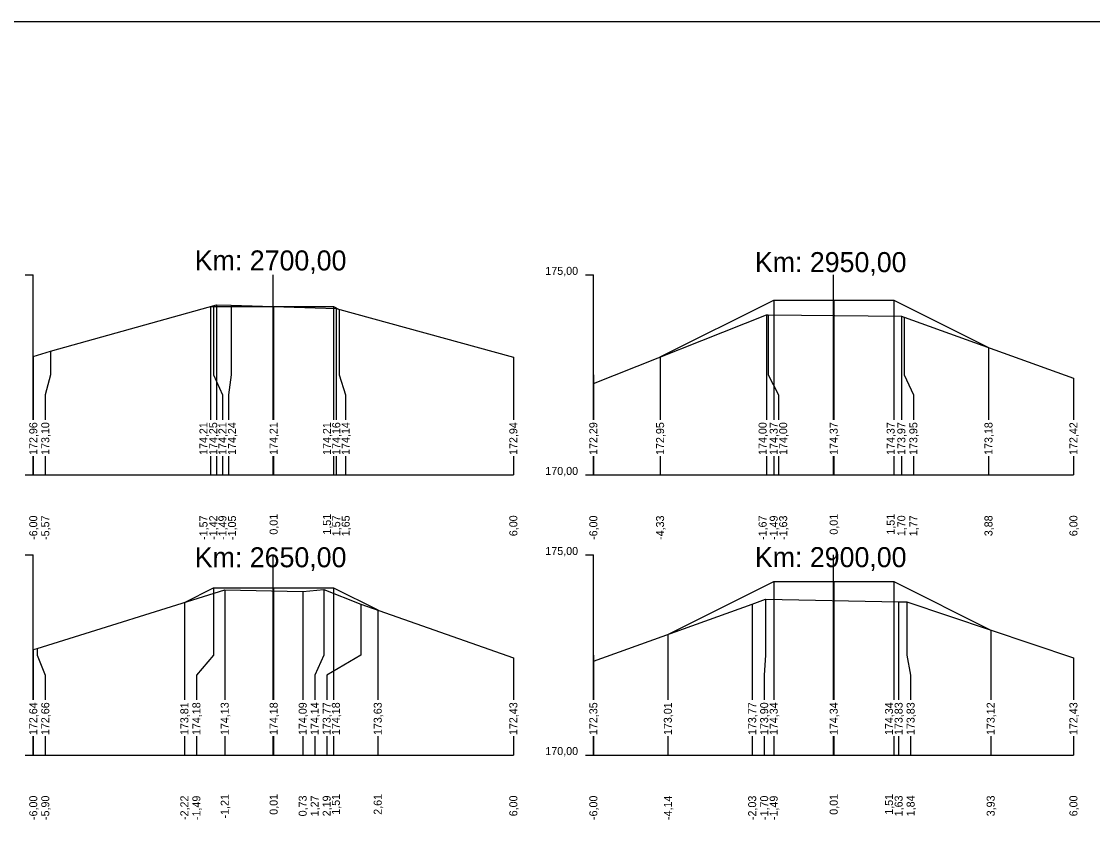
# Model space of a CAD drawing. Extents: x -614174 to -599765, y -1185887 to -1181080.
# Drawn here: x -601074.69 to -601047.91, y -1184510.88 to -1184490.94 of the extents above; entities that cross this region are included whole.
import ezdxf

# ---------------------------------------------------------------- set-up
doc = ezdxf.new("R2010")
doc.units = 0
for name, color, linetype in [('11', 7, 'Continuous'), ('16', 7, 'Continuous'), ('21', 7, 'Continuous'), ('28', 7, 'Continuous'), ('59', 7, 'Continuous'), ('8', 7, 'Continuous'), ('návrh', 7, 'Continuous')]:
    doc.layers.add(name, color=color, linetype=linetype)

msp = doc.modelspace()

# ---------------------------------------------------------------- linework, layer by layer
for points in [[(-601074.389, -1184499.308), (-601073.958, -1184499.173), (-601069.808, -1184498.019), (-601069.44, -1184498.026), (-601066.816, -1184498.111), (-601062.389, -1184499.329)], [(-601069.961, -1184498.061), (-601069.881, -1184498.061), (-601068.381, -1184498.061), (-601066.881, -1184498.061), (-601066.739, -1184498.132)], [(-601069.881, -1184498.061), (-601069.881, -1184498.061), (-601069.881, -1184498.061)], [(-601068.381, -1184498.061), (-601068.381, -1184498.061), (-601068.381, -1184498.061)], [(-601066.881, -1184498.061), (-601066.881, -1184498.061), (-601066.881, -1184498.061)], [(-601058.721, -1184499.322), (-601055.881, -1184497.902), (-601054.381, -1184497.902), (-601052.881, -1184497.902), (-601050.512, -1184499.086)], [(-601055.881, -1184497.902), (-601055.881, -1184497.902), (-601055.881, -1184497.902)], [(-601054.381, -1184497.902), (-601054.381, -1184497.902), (-601054.381, -1184497.902)], [(-601052.881, -1184497.902), (-601052.881, -1184497.902), (-601052.881, -1184497.902)], [(-601060.389, -1184499.981), (-601056.062, -1184498.271), (-601056.016, -1184498.272), (-601052.69, -1184498.302), (-601052.623, -1184498.324), (-601048.389, -1184499.853)], [(-601058.721, -1184499.322), (-601058.721, -1184499.322), (-601058.722, -1184499.322)], [(-601058.527, -1184506.257), (-601055.881, -1184504.934), (-601054.381, -1184504.934), (-601052.881, -1184504.934), (-601050.457, -1184506.146)], [(-601055.881, -1184504.934), (-601055.881, -1184504.934), (-601055.881, -1184504.934)], [(-601054.381, -1184504.934), (-601054.381, -1184504.934), (-601054.381, -1184504.934)], [(-601052.881, -1184504.934), (-601052.881, -1184504.934), (-601052.881, -1184504.934)], [(-601074.389, -1184506.633), (-601074.289, -1184506.608), (-601069.604, -1184505.143), (-601067.655, -1184505.184), (-601067.124, -1184505.132), (-601066.201, -1184505.495), (-601062.389, -1184506.842)], [(-601070.612, -1184505.458), (-601069.881, -1184505.093), (-601068.381, -1184505.093), (-601066.881, -1184505.093), (-601065.779, -1184505.644)], [(-601069.881, -1184505.093), (-601069.881, -1184505.093), (-601069.881, -1184505.093)], [(-601068.381, -1184505.093), (-601068.381, -1184505.093), (-601068.381, -1184505.093)], [(-601066.881, -1184505.093), (-601066.881, -1184505.093), (-601066.881, -1184505.093)], [(-601070.613, -1184505.459), (-601070.612, -1184505.458), (-601070.612, -1184505.458)], [(-601060.389, -1184506.922), (-601056.419, -1184505.503), (-601056.09, -1184505.373), (-601052.759, -1184505.439), (-601052.551, -1184505.44), (-601048.389, -1184506.843)], [(-601058.527, -1184506.257), (-601058.527, -1184506.257), (-601058.527, -1184506.257)]]:
    msp.add_lwpolyline(points)
at = {"layer": '11'}
for points in [[(-601069.961, -1184498.061), (-601069.961, -1184499.77), (-601069.961, -1184500.27), (-601069.961, -1184500.892)], [(-601069.881, -1184498.061), (-601069.881, -1184499.77), (-601069.661, -1184500.27), (-601069.661, -1184500.892)], [(-601069.808, -1184498.019), (-601069.808, -1184499.77), (-601069.808, -1184500.27), (-601069.808, -1184500.892)], [(-601069.44, -1184498.026), (-601069.44, -1184499.77), (-601069.508, -1184500.27), (-601069.508, -1184500.892)], [(-601068.381, -1184498.061), (-601068.381, -1184499.77), (-601068.381, -1184500.27), (-601068.381, -1184500.892)], [(-601066.881, -1184498.061), (-601066.881, -1184499.77), (-601066.881, -1184500.27), (-601066.881, -1184500.892)], [(-601066.816, -1184498.111), (-601066.816, -1184499.77), (-601066.816, -1184500.27), (-601066.816, -1184500.892)], [(-601055.881, -1184497.902), (-601055.881, -1184499.77), (-601055.881, -1184500.27), (-601055.881, -1184500.892)], [(-601054.381, -1184497.902), (-601054.381, -1184499.77), (-601054.381, -1184500.27), (-601054.381, -1184500.892)], [(-601052.881, -1184497.902), (-601052.881, -1184499.77), (-601052.881, -1184500.27), (-601052.881, -1184500.892)], [(-601066.739, -1184498.132), (-601066.739, -1184499.77), (-601066.581, -1184500.27), (-601066.581, -1184500.892)], [(-601056.062, -1184498.271), (-601056.062, -1184499.77), (-601056.062, -1184500.27), (-601056.062, -1184500.892)], [(-601056.016, -1184498.272), (-601056.016, -1184499.77), (-601055.762, -1184500.27), (-601055.762, -1184500.892)], [(-601052.69, -1184498.302), (-601052.69, -1184499.77), (-601052.69, -1184500.27), (-601052.69, -1184500.892)], [(-601052.623, -1184498.324), (-601052.623, -1184499.77), (-601052.39, -1184500.27), (-601052.39, -1184500.892)], [(-601073.958, -1184499.173), (-601073.958, -1184499.77), (-601074.089, -1184500.27), (-601074.089, -1184500.892)], [(-601050.512, -1184499.086), (-601050.512, -1184499.77), (-601050.512, -1184500.27), (-601050.512, -1184500.892)], [(-601074.389, -1184499.308), (-601074.389, -1184499.77), (-601074.389, -1184500.27), (-601074.389, -1184500.892)], [(-601062.389, -1184499.329), (-601062.389, -1184499.77), (-601062.389, -1184500.27), (-601062.389, -1184500.892)], [(-601058.721, -1184499.322), (-601058.721, -1184499.77), (-601058.721, -1184500.27), (-601058.721, -1184500.892)], [(-601060.389, -1184499.981), (-601060.389, -1184499.77), (-601060.389, -1184500.27), (-601060.389, -1184500.892)], [(-601048.389, -1184499.853), (-601048.389, -1184500.27), (-601048.389, -1184500.892)], [(-601074.389, -1184501.8), (-601074.389, -1184502.27)], [(-601074.089, -1184501.8), (-601074.089, -1184502.27)], [(-601069.961, -1184501.8), (-601069.961, -1184502.27)], [(-601069.808, -1184501.8), (-601069.808, -1184502.27)], [(-601069.661, -1184501.8), (-601069.661, -1184502.27)], [(-601069.508, -1184501.8), (-601069.508, -1184502.27)], [(-601068.381, -1184501.8), (-601068.381, -1184502.27)], [(-601066.881, -1184501.8), (-601066.881, -1184502.27)], [(-601066.816, -1184501.8), (-601066.816, -1184502.27)], [(-601066.581, -1184501.8), (-601066.581, -1184502.27)], [(-601062.389, -1184501.8), (-601062.389, -1184502.27)], [(-601060.389, -1184501.8), (-601060.389, -1184502.27)], [(-601058.721, -1184501.8), (-601058.721, -1184502.27)], [(-601056.062, -1184501.8), (-601056.062, -1184502.27)], [(-601055.881, -1184501.8), (-601055.881, -1184502.27)], [(-601055.762, -1184501.8), (-601055.762, -1184502.27)], [(-601054.381, -1184501.8), (-601054.381, -1184502.27)], [(-601052.881, -1184501.8), (-601052.881, -1184502.27)], [(-601052.69, -1184501.8), (-601052.69, -1184502.27)], [(-601052.39, -1184501.8), (-601052.39, -1184502.27)], [(-601050.512, -1184501.8), (-601050.512, -1184502.27)], [(-601048.389, -1184501.8), (-601048.389, -1184502.27)], [(-601055.881, -1184504.934), (-601055.881, -1184506.77), (-601055.881, -1184507.27), (-601055.881, -1184507.892)], [(-601054.381, -1184504.934), (-601054.381, -1184506.77), (-601054.381, -1184507.27), (-601054.381, -1184507.892)], [(-601052.881, -1184504.934), (-601052.881, -1184506.77), (-601052.881, -1184507.27), (-601052.881, -1184507.892)], [(-601069.881, -1184505.093), (-601069.881, -1184506.77), (-601070.312, -1184507.27), (-601070.312, -1184507.892)], [(-601069.604, -1184505.143), (-601069.604, -1184506.77), (-601069.604, -1184507.27), (-601069.604, -1184507.892)], [(-601068.381, -1184505.093), (-601068.381, -1184506.77), (-601068.381, -1184507.27), (-601068.381, -1184507.892)], [(-601067.655, -1184505.184), (-601067.655, -1184506.77), (-601067.655, -1184507.27), (-601067.655, -1184507.892)], [(-601067.124, -1184505.132), (-601067.124, -1184506.77), (-601067.355, -1184507.27), (-601067.355, -1184507.892)], [(-601066.881, -1184505.093), (-601066.881, -1184506.77), (-601066.881, -1184507.27), (-601066.881, -1184507.892)], [(-601070.612, -1184505.458), (-601070.612, -1184506.77), (-601070.612, -1184507.27), (-601070.612, -1184507.892)], [(-601066.201, -1184505.495), (-601066.201, -1184506.77), (-601067.055, -1184507.27), (-601067.055, -1184507.892)], [(-601056.419, -1184505.503), (-601056.419, -1184506.77), (-601056.419, -1184507.27), (-601056.419, -1184507.892)], [(-601056.09, -1184505.373), (-601056.09, -1184506.77), (-601056.119, -1184507.27), (-601056.119, -1184507.892)], [(-601052.759, -1184505.439), (-601052.759, -1184506.77), (-601052.759, -1184507.27), (-601052.759, -1184507.892)], [(-601052.551, -1184505.44), (-601052.551, -1184506.77), (-601052.459, -1184507.27), (-601052.459, -1184507.892)], [(-601065.779, -1184505.644), (-601065.779, -1184506.77), (-601065.779, -1184507.27), (-601065.779, -1184507.892)], [(-601050.457, -1184506.146), (-601050.457, -1184506.77), (-601050.457, -1184507.27), (-601050.457, -1184507.892)], [(-601058.527, -1184506.257), (-601058.527, -1184506.77), (-601058.527, -1184507.27), (-601058.527, -1184507.892)], [(-601074.389, -1184506.633), (-601074.389, -1184506.77), (-601074.389, -1184507.27), (-601074.389, -1184507.892)], [(-601074.289, -1184506.608), (-601074.289, -1184506.77), (-601074.089, -1184507.27), (-601074.089, -1184507.892)], [(-601062.389, -1184506.842), (-601062.389, -1184507.27), (-601062.389, -1184507.892)], [(-601060.389, -1184506.922), (-601060.389, -1184506.77), (-601060.389, -1184507.27), (-601060.389, -1184507.892)], [(-601048.389, -1184506.843), (-601048.389, -1184507.27), (-601048.389, -1184507.892)], [(-601074.389, -1184508.8), (-601074.389, -1184509.27)], [(-601074.089, -1184508.8), (-601074.089, -1184509.27)], [(-601070.612, -1184508.8), (-601070.612, -1184509.27)], [(-601070.312, -1184508.8), (-601070.312, -1184509.27)], [(-601069.604, -1184508.8), (-601069.604, -1184509.27)], [(-601068.381, -1184508.8), (-601068.381, -1184509.27)], [(-601067.655, -1184508.8), (-601067.655, -1184509.27)], [(-601067.355, -1184508.8), (-601067.355, -1184509.27)], [(-601067.055, -1184508.8), (-601067.055, -1184509.27)], [(-601066.881, -1184508.8), (-601066.881, -1184509.27)], [(-601065.779, -1184508.8), (-601065.779, -1184509.27)], [(-601062.389, -1184508.8), (-601062.389, -1184509.27)], [(-601060.389, -1184508.8), (-601060.389, -1184509.27)], [(-601058.527, -1184508.8), (-601058.527, -1184509.27)], [(-601056.419, -1184508.8), (-601056.419, -1184509.27)], [(-601056.119, -1184508.8), (-601056.119, -1184509.27)], [(-601055.881, -1184508.8), (-601055.881, -1184509.27)], [(-601054.381, -1184508.8), (-601054.381, -1184509.27)], [(-601052.881, -1184508.8), (-601052.881, -1184509.27)], [(-601052.759, -1184508.8), (-601052.759, -1184509.27)], [(-601052.459, -1184508.8), (-601052.459, -1184509.27)], [(-601050.457, -1184508.8), (-601050.457, -1184509.27)], [(-601048.389, -1184508.8), (-601048.389, -1184509.27)]]:
    msp.add_lwpolyline(points, dxfattribs=at)
at = {"layer": '16'}
for p, q in [((-601074.389, -1184502.27), (-601062.389, -1184502.27)), ((-601060.389, -1184502.27), (-601048.389, -1184502.27)), ((-601074.389, -1184509.27), (-601062.389, -1184509.27)), ((-601060.389, -1184509.27), (-601048.389, -1184509.27))]:
    msp.add_line(p, q, dxfattribs=at)
for points in [[(-601066.739, -1184498.132), (-601066.739, -1184498.132), (-601066.739, -1184498.132)], [(-601050.512, -1184499.086), (-601050.512, -1184499.086), (-601050.512, -1184499.087)], [(-601065.778, -1184505.644), (-601065.779, -1184505.644), (-601065.779, -1184505.644)], [(-601050.457, -1184506.146), (-601050.457, -1184506.146), (-601050.457, -1184506.146)]]:
    msp.add_lwpolyline(points, dxfattribs=at)
at = {"layer": '21'}
for p, q in [((-601074.589, -1184497.27), (-601074.389, -1184497.27)), ((-601060.589, -1184497.27), (-601060.389, -1184497.27)), ((-601074.589, -1184502.27), (-601074.389, -1184502.27)), ((-601060.589, -1184502.27), (-601060.389, -1184502.27)), ((-601074.589, -1184504.27), (-601074.389, -1184504.27)), ((-601060.589, -1184504.27), (-601060.389, -1184504.27)), ((-601074.589, -1184509.27), (-601074.389, -1184509.27)), ((-601060.589, -1184509.27), (-601060.389, -1184509.27))]:
    msp.add_line(p, q, dxfattribs=at)
at = {"layer": '28'}
for p, q in [((-601068.389, -1184500.892), (-601068.389, -1184497.27)), ((-601054.389, -1184500.892), (-601054.389, -1184497.27)), ((-601068.389, -1184502.27), (-601068.389, -1184501.8)), ((-601054.389, -1184502.27), (-601054.389, -1184501.8)), ((-601068.389, -1184507.892), (-601068.389, -1184504.27)), ((-601054.389, -1184507.892), (-601054.389, -1184504.27)), ((-601068.389, -1184509.27), (-601068.389, -1184508.8)), ((-601054.389, -1184509.27), (-601054.389, -1184508.8))]:
    msp.add_line(p, q, dxfattribs=at)
at = {"layer": '8'}
for p, q in [((-601074.389, -1184500.892), (-601074.389, -1184497.27)), ((-601060.389, -1184500.892), (-601060.389, -1184497.27)), ((-601074.389, -1184502.27), (-601074.389, -1184501.8)), ((-601060.389, -1184502.27), (-601060.389, -1184501.8)), ((-601074.389, -1184507.892), (-601074.389, -1184504.27)), ((-601060.389, -1184507.892), (-601060.389, -1184504.27)), ((-601074.389, -1184509.27), (-601074.389, -1184508.8)), ((-601060.389, -1184509.27), (-601060.389, -1184508.8))]:
    msp.add_line(p, q, dxfattribs=at)
at = {"layer": 'návrh'}
msp.add_line((-601090.944, -1184490.936), (-600943.944, -1184490.936), dxfattribs=at)

# ---------------------------------------------------------------- texts
msp.add_text('+', height=0.001).set_placement((-601069.961, -1184498.062))
at = {"layer": '16'}
for s, p in [('172,96', (-601074.289, -1184501.77)), ('173,10', (-601073.989, -1184501.77)), ('174,21', (-601070.034, -1184501.77)), ('174,25', (-601069.791, -1184501.77)), ('174,21', (-601069.561, -1184501.77)), ('174,24', (-601069.322, -1184501.77)), ('174,21', (-601068.281, -1184501.77)), ('174,21', (-601066.948, -1184501.77)), ('174,16', (-601066.716, -1184501.77)), ('174,14', (-601066.481, -1184501.77)), ('172,94', (-601062.289, -1184501.77)), ('172,29', (-601060.289, -1184501.77)), ('172,95', (-601058.621, -1184501.77)), ('174,00', (-601056.059, -1184501.77)), ('174,37', (-601055.781, -1184501.77)), ('174,00', (-601055.544, -1184501.77)), ('174,37', (-601054.281, -1184501.77)), ('174,37', (-601052.858, -1184501.77)), ('173,97', (-601052.59, -1184501.77)), ('173,95', (-601052.29, -1184501.77)), ('173,18', (-601050.412, -1184501.77)), ('172,42', (-601048.289, -1184501.77)), ('172,64', (-601074.289, -1184508.77)), ('172,66', (-601073.989, -1184508.77)), ('173,81', (-601070.512, -1184508.77)), ('174,18', (-601070.212, -1184508.77)), ('174,13', (-601069.504, -1184508.77)), ('174,18', (-601068.281, -1184508.77)), ('174,09', (-601067.555, -1184508.77)), ('174,14', (-601067.255, -1184508.77)), ('173,77', (-601066.955, -1184508.77)), ('174,18', (-601066.726, -1184508.77)), ('173,63', (-601065.679, -1184508.77)), ('172,43', (-601062.289, -1184508.77)), ('172,35', (-601060.289, -1184508.77)), ('173,01', (-601058.427, -1184508.77)), ('173,77', (-601056.319, -1184508.77)), ('173,90', (-601056.019, -1184508.77)), ('174,34', (-601055.781, -1184508.77)), ('174,34', (-601054.281, -1184508.77)), ('174,34', (-601052.899, -1184508.77)), ('173,83', (-601052.659, -1184508.77)), ('173,83', (-601052.359, -1184508.77)), ('173,12', (-601050.357, -1184508.77)), ('172,43', (-601048.289, -1184508.77))]:
    msp.add_text(s, height=0.2, rotation=90, dxfattribs=at).set_placement(p)
at = {"layer": '21'}
for s, p in [('175,00', (-601061.589, -1184497.27)), ('170,00', (-601061.589, -1184502.27)), ('175,00', (-601061.589, -1184504.27)), ('170,00', (-601061.589, -1184509.27))]:
    msp.add_text(s, height=0.2, dxfattribs=at).set_placement(p)
at = {"layer": '28'}
for s, p in [('Km: 2700,00', (-601070.352, -1184497.159)), ('Km: 2950,00', (-601056.352, -1184497.201)), ('Km: 2650,00', (-601070.352, -1184504.577)), ('Km: 2900,00', (-601056.352, -1184504.574))]:
    msp.add_text(s, height=0.5, dxfattribs=at).set_placement(p)
at = {"layer": '59'}
for s, p in [('-6,00', (-601074.289, -1184503.893)), ('-5,57', (-601073.989, -1184503.894)), ('-1,57', (-601070.034, -1184503.894)), ('-1,42', (-601069.791, -1184503.892)), ('-1,49', (-601069.561, -1184503.894)), ('-1,05', (-601069.322, -1184503.895)), ('0,01', (-601068.281, -1184503.762)), ('1,51', (-601066.948, -1184503.762)), ('1,57', (-601066.716, -1184503.801)), ('1,65', (-601066.481, -1184503.802)), ('6,00', (-601062.289, -1184503.8)), ('-6,00', (-601060.289, -1184503.893)), ('-4,33', (-601058.621, -1184503.894)), ('-1,67', (-601056.059, -1184503.894)), ('-1,49', (-601055.781, -1184503.894)), ('-1,63', (-601055.544, -1184503.894)), ('0,01', (-601054.281, -1184503.762)), ('1,51', (-601052.858, -1184503.762)), ('1,70', (-601052.59, -1184503.8)), ('1,77', (-601052.29, -1184503.801)), ('3,88', (-601050.412, -1184503.801)), ('6,00', (-601048.289, -1184503.8)), ('-6,00', (-601074.289, -1184510.893)), ('-5,90', (-601073.989, -1184510.893)), ('-2,22', (-601070.512, -1184510.892)), ('-1,49', (-601070.212, -1184510.894)), ('-1,21', (-601069.504, -1184510.855)), ('0,01', (-601068.281, -1184510.762)), ('0,73', (-601067.555, -1184510.801)), ('1,27', (-601067.255, -1184510.801)), ('2,19', (-601066.955, -1184510.801)), ('1,51', (-601066.726, -1184510.762)), ('2,61', (-601065.679, -1184510.762)), ('6,00', (-601062.289, -1184510.8)), ('-6,00', (-601060.289, -1184510.893)), ('-4,14', (-601058.427, -1184510.893)), ('-2,03', (-601056.319, -1184510.894)), ('-1,70', (-601056.019, -1184510.893)), ('-1,49', (-601055.781, -1184510.894)), ('0,01', (-601054.281, -1184510.762)), ('1,51', (-601052.899, -1184510.762)), ('1,63', (-601052.659, -1184510.801)), ('1,84', (-601052.359, -1184510.8)), ('3,93', (-601050.357, -1184510.801)), ('6,00', (-601048.289, -1184510.8))]:
    msp.add_text(s, height=0.2, rotation=90, dxfattribs=at).set_placement(p)

doc.saveas('drawing.dxf')
